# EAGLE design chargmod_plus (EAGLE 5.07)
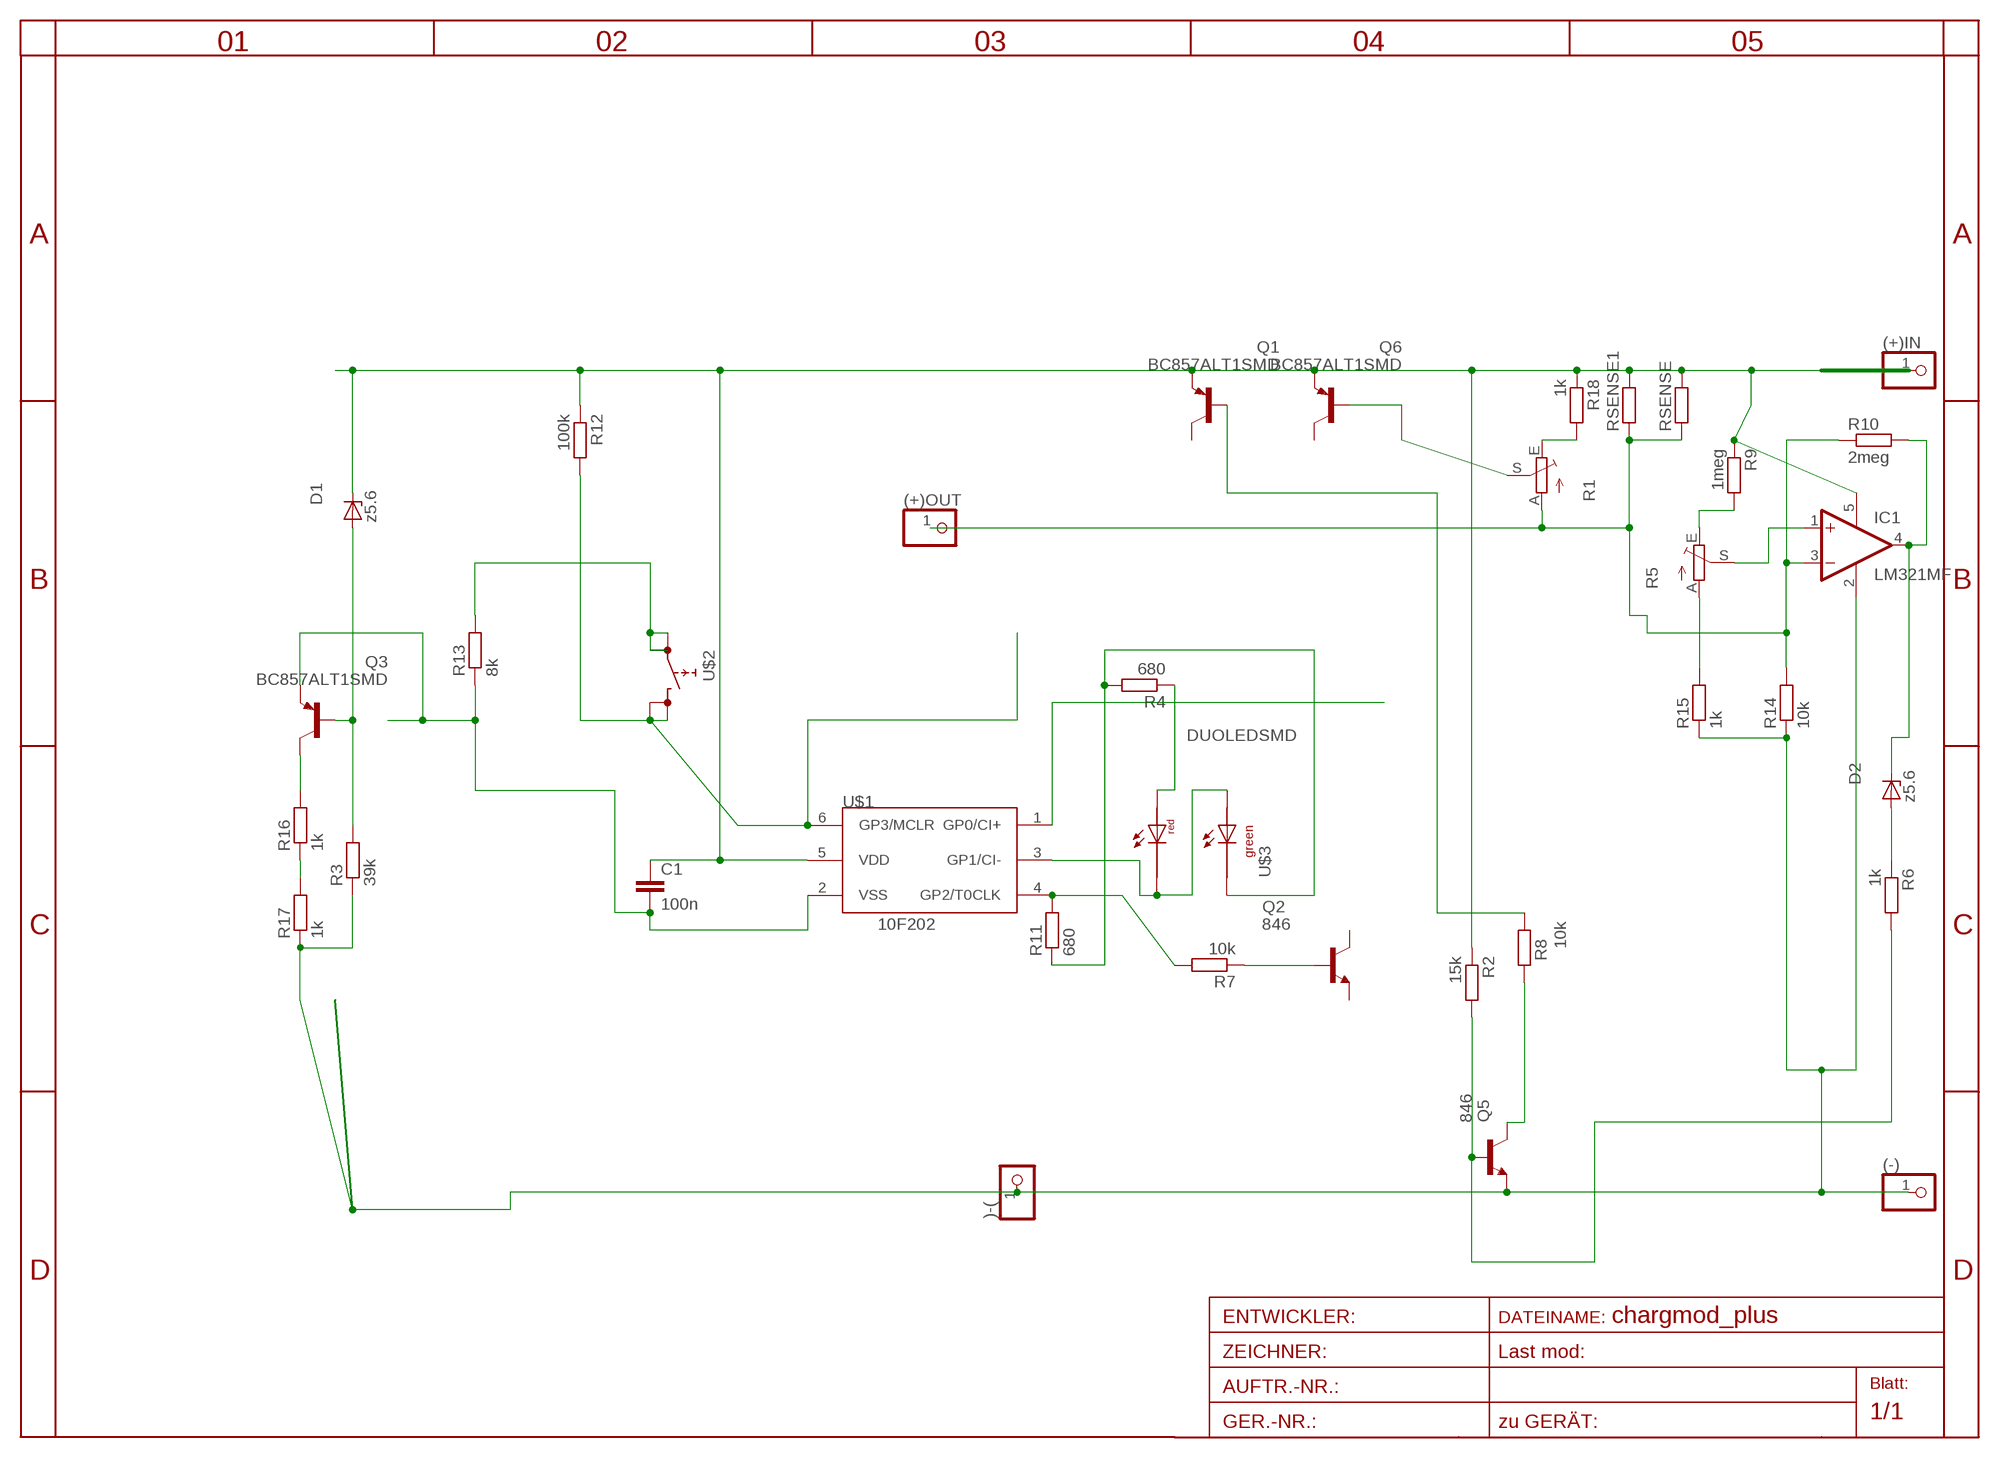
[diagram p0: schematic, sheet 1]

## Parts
(+)IN  PINHD-1X11MM6  [1X1MM8]
(+)OUT  PINHD-1X11MM6  [1X1MM8]
(-)  PINHD-1X11MM6  [1X1MM8]
)-(  PINHD-1X11MM6  [1X1MM8]
C1  100n  C-EUC1206  [C1206]
D1  z5.6  ZENER-DIODESOD80C  [SOD80C]
D2  z5.6  ZENER-DIODESOD80C  [SOD80C]
IC1  LM321MF  [SOT23-5]
Q1  BC857ALT1SMD  [SOT23-BEC]
Q2  846  BC846BSMD  [SOT23]
Q3  BC857ALT1SMD  [SOT23-BEC]
Q5  846  BC846BSMD  [SOT23]
Q6  BC857ALT1SMD  [SOT23-BEC]
R1  TRIM_EU-S64W  [S64W]
R2  15k  R-EU_R0805  [R0805]
R3  39k  R-EU_R0805  [R0805]
R4  680  R-EU_R0805  [R0805]
R5  TRIM_EU-S64W  [S64W]
R6  1k  R-EU_R1206  [R1206]
R7  10k  R-EU_R1206  [R1206]
R8  10k  R-EU_R0805  [R0805]
R9  1meg  R-EU_R0805  [R0805]
R10  2meg  R-EU_R0805  [R0805]
R11  680  R-EU_R0805  [R0805]
R12  100k  R-EU_R0805  [R0805]
R13  8k  R-EU_R0805  [R0805]
R14  10k  R-EU_R0805  [R0805]
R15  1k  R-EU_R0805  [R0805]
R16  1k  R-EU_R1206  [R1206]
R17  1k  R-EU_R1206  [R1206]
R18  1k  R-EU_R1206  [R1206]
RSENSE  R-EU_0207/10  [0207/10]
RSENSE1  R-EU_0207/10  [0207/10]
U$1  10F202  PIC10F202OT  [SOT23-6]
U$2  SMD4  [SMD4]
U$3  DUOLEDSMD  [DUOLEDSMD]

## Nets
GP2: R7.2 R11.2 U$1.4(GP2/T0CLK)
GP3: R12.2 U$1.6(GP3/MCLR) U$2.3(2.1) U$2.4(2.2)
N$2: U$1.3(GP1/CI-) U$3.AGRN U$3.CRED
N$3: Q5.1(B) R2.2 R6.2
N$4: D1.A Q3.B R3.2
N$5: R4.1 U$3.ARED
N$6: R4.2 R11.1 U$3.CGRN
N$7: Q1.B R8.1
N$8: Q3.C R16.2
N$9: (+)OUT.1 IC1.3(-IN) R1.A R10.1 R14.2 RSENSE1.1 RSENSE.1
N$10: Q2.1(B) R7.1
N$11: C1.2 Q3.E R13.1 U$1.2(VSS)
N$12: U$1.1(GP0/CI+)
N$13: D2.C IC1.4(OUT) R10.2
N$14: R16.1 R17.2
N$15: R13.2 U$2.1(1.1) U$2.2(1.2)
N$16: IC1.1(+IN) R5.S
N$17: Q6.B R1.S
N$19: R5.A R15.2
N$20: Q5.3(C) R8.2
N$21: R5.E R9.2
N$22: R1.E R18.2
N$23: D2.A R6.1
V+IN: (+)IN.1 C1.1 D1.C IC1.5(V+) Q1.E Q6.E R2.1 R9.1 R12.1 R18.1 RSENSE1.2 RSENSE.2 U$1.5(VDD)
VSS: (-).1 )-(.1 IC1.2(V-) Q5.2(E) R3.1 R14.1 R15.1 R17.1
Unconnected: Q1.C Q2.2(E) Q2.3(C) Q6.C

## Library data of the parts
(+)IN (+)OUT (-) )-( = pinhead:PINHD-1X1: PIN HEADER
C1 = rcl:C-EU: CAPACITOR, European symbol
D1 D2 = diode-1:ZENER-DIODE: Z-Diode
IC1 = linear:LM321?*: Low Power Single Op Amp Source: http://cache.national.com/ds/LM/LM321.pdf
Q1 Q3 Q6 = transistor-pnp:BC857*: PNP Transistror
Q2 Q5 = transistor-npn:BC846*: NPN Transistor
R1 R5 = pot:TRIM_EU-: POTENTIOMETER
R2-R4 R6-R18 RSENSE RSENSE1 = rcl:R-EU_: RESISTOR, European symbol
U$1 = microchip-5:PIC10F2*: uPC nW 0,25/0,5k Program Flash memory Comparator
U$2 = switch:SMD4
U$3 = led:DUOLEDSMD

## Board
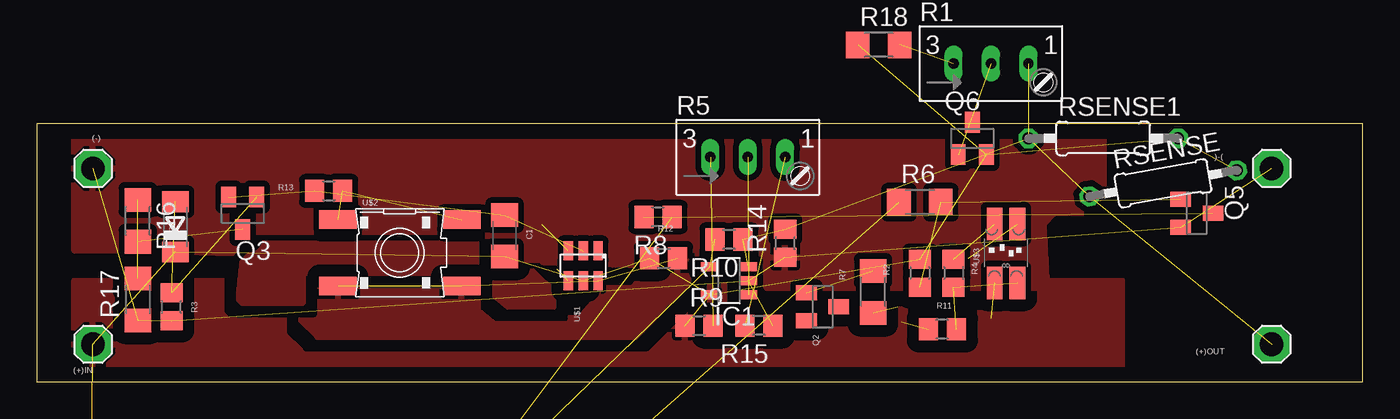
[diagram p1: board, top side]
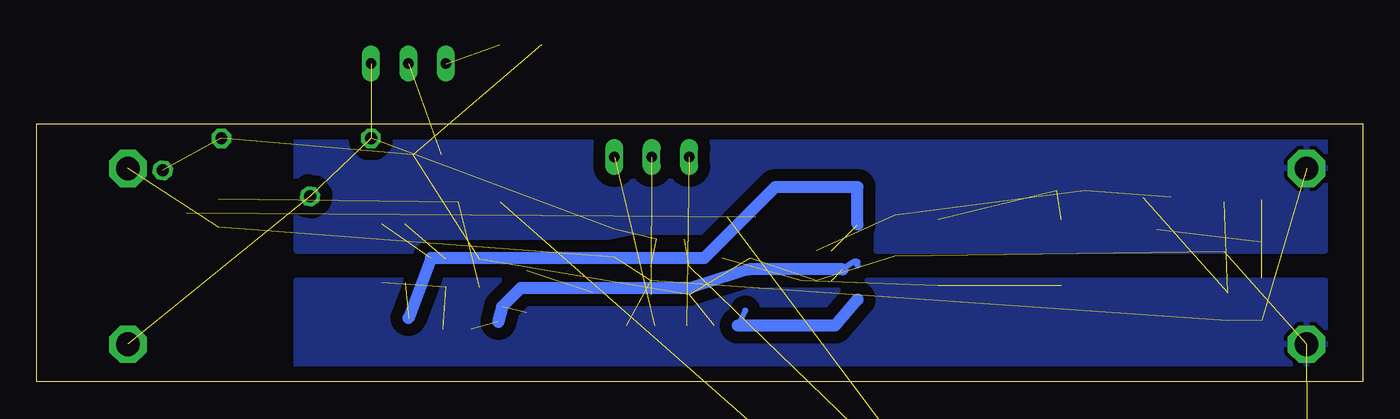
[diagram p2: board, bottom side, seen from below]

Size 90 x 17.5 mm. Coordinates in mm from the lower left corner, seen from the top.
Outline: 0,0 90,0 90,17.5 0,17.5 0,0
Copper layers (1*16): Top 0.035mm / dielectric 1.5mm / Bottom 0.035mm
Design rules "default *": minimum track width 10mil, minimum drill 14mil, track to track 8mil, track to pad 8mil, pad to pad 8mil, via to via 8mil, smd to smd 8mil, copper to edge 40mil, drill to drill 8mil, minimum pad ring 10mil, minimum via ring 8mil, stop-mask expansion 4mil, vias tented up to drill 0mil, thermal gap 10mil

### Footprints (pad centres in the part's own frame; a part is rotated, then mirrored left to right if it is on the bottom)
1X1MM8 = drill 1.6 pad 2.54 octagon: 1 0,0
C1206 = smd 1.6 x 1.8: 1 -1.4,0; 2 1.4,0
SOD80C = smd 1.4 x 1.8: A 1.7,0; C -1.7,0
SOT23-5 = smd 0.6 x 1.2: 1 -0.95,-1.306; 2 0,-1.306; 3 0.95,-1.306; 4 0.95,1.306; 5 -0.95,1.306
SOT23-BEC = smd 1 x 1.4: B -0.95,-1.1; C 0,1.1; E 0.95,-1.1
SOT23 = smd 1 x 1.4: 1 -0.95,-1.1; 2 0.95,-1.1; 3 0,1.1
S64W = drill 0.7 long: A 2.54,1.27; E -2.54,1.27; S 0,1.27
R0805 = smd 1.3 x 1.5: 1 -0.95,0; 2 0.95,0
R1206 = smd 1.6 x 1.803: 1 -1.422,0; 2 1.422,0
0207/10 = drill 0.813 octagon: 1 -5.08,0; 2 5.08,0
SOT23-6 = smd 0.635 x 1.27: 1 -1.016,-1.016; 2 0,-1.016; 3 1.016,-1.016; 4 1.016,1.016; 5 0,1.016; 6 -1.016,1.016
SMD4 = smd 2.54 x 1.27: 1 -4.2,2.25; 2 4.2,2.25; 3 -4.2,-2.25; 4 4.2,-2.25
DUOLEDSMD = smd 1.067 x 2.184: AGRN 0.77,1.95; ARED -0.77,1.95; CGRN 0.77,-2.05; CRED -0.77,-2.05

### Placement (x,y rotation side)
(+)IN  3.81,2.54 0 top
(+)OUT  83.82,2.54 0 top
(-)  3.81,14.48 0 top
)-(  83.82,14.48 0 top
C1  31.75,9.91 90 top
D1  9.4,10.51 90 top
D2  not placed on the board
IC1  46.99,6.86 90 top
Q1  not placed on the board
Q2  53.34,5.08 270 top
Q3  13.97,11.43 180 top
Q5  78.74,11.43 270 top
Q6  63.5,16.51 0 top
R1  not placed on the board
R2  59.94,7.37 270 top
R3  9.14,5.08 90 top
R4  62.23,7.37 270 top
R5  48.26,13.97 0 top
R6  59.94,12.19 0 top
R7  56.77,6.1 270 top
R8  42.16,11.18 180 top
R9  44.96,3.81 0 top
R10  46.99,9.65 180 top
R11  61.47,3.56 180 top
R12  42.55,8.38 0 top
R13  19.81,12.95 0 top
R14  50.8,9.4 90 top
R15  49.02,3.81 180 top
R16  6.86,10.92 270 top
R17  6.86,5.59 90 top
R18  not placed on the board
RSENSE  76.45,13.46 10 top
RSENSE1  72.39,16.51 0 top
U$1  37.08,7.87 180 top
U$2  24.64,8.75 0 top
U$3  65.79,8.75 0 top

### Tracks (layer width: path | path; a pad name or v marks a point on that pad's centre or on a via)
GP2  (3 unrouted)
  Bottom 0.406: 35.31,7.62 34.54,8.13 34.29,8.13 34.29,7.87
  Bottom 0.813: 35.31,7.62 41.66,7.62 45.72,6.35 57.15,6.35 58.42,5.08 58.67,4.06
GP3  (3 unrouted)
  pour Top (isolate 0.813, rank 2): 17.78,5.59 17.78,4.32 19.05,3.05 40.64,3.05 45.47,7.87 45.21,8.13 43.18,8.13 41.91,6.86 40.89,6.86 40.39,6.35 38.61,6.35 36.83,4.32 31.75,4.32 29.21,6.86 19.05,6.86
N$2  (3 unrouted)
  Bottom 0.813: 34.29,10.67 34.29,13.21 39.88,13.21 44.7,8.38 63.25,8.38 64.77,4.32
N$3  (2 unrouted)
N$4  (2 unrouted)
N$5  (1 unrouted)
N$6  (2 unrouted)
N$7  (1 unrouted)
N$8  (1 unrouted)
N$9  (6 unrouted)
N$10  (1 unrouted)
N$11  (3 unrouted)
N$13  (2 unrouted)
N$14  (1 unrouted)
N$15  (2 unrouted)
N$16  (1 unrouted)
N$17  (1 unrouted)
N$19  (1 unrouted)
N$20  (1 unrouted)
N$21  (1 unrouted)
N$22  (1 unrouted)
N$23  (1 unrouted)
V+IN  (12 unrouted)
  pour Top (isolate 0.813, rank 5): 2.54,6.86 73.66,6.86 73.66,0.51 2.54,0.51
  pour Top: 73.66,5.59 73.66,3.05 69.85,3.05 69.85,4.32 71.12,5.59
  pour Bottom (isolate 0.813, rank 5): 2.54,6.86 72.39,6.86 72.39,0.51 2.54,0.51
VDD
  Bottom 0.406: 42.42,3.81 41.91,4.83
  Bottom 0.813: 42.42,3.81 35.81,3.81 34.29,5.59
  pour Top (isolate 0.813): 13.97,8.13 15.24,9.4 31.75,9.4 34.29,6.86 35.05,6.35 35.05,5.08 32,5.08 29.21,7.37 18.03,7.37 18.03,5.33 13.97,5.33 13.72,5.59
VSS  (7 unrouted)
  pour Top (isolate 0.406, rank 5): 6.35,8.89 2.54,8.89 2.54,16.51 72.39,16.51 72.39,11.43 69.09,11.43 68.33,10.67 68.58,6.35 49.53,6.35 49.53,7.62
  pour Bottom (isolate 0.813, rank 5): 33.02,8.89 2.54,8.89 2.54,16.51 72.39,16.51 72.39,8.89 55.88,8.89 49.53,10.16 34.29,10.16 33.02,11.43

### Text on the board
tTest: 500u | 5u | 2m | 5m | 2m | 500u | 1m | 500u | 5m
Document: vin-10/2m | Vin*1k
